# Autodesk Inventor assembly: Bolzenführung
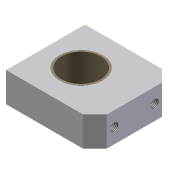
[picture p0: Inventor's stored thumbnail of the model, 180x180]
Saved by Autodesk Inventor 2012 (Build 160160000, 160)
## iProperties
Company: CAD-Verlag
Created: 2004-09
Part Number: Bolzenführung
Document SubType Name: Assembly
Designer: Greiling
Manufacturer: Standard
Standards Organization: Custom
Checked By: Jürgen Kronas
Stock Number: 10-10016
Author: Juergen Kronas
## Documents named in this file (3)
- C:\DemoDaten2012\CAD Daten\Daten Vault 2012 Inventor\Kapitel 4\Anschlag\Bolzenführung.iam
- C:\DemoDaten2012\CAD Daten\Daten Vault 2012 Inventor\Kapitel 4\Anschlag\Bolzenführung_einzel.ipt
- C:\DemoDaten2012\CAD Daten\Daten Vault 2012 Inventor\Kapitel 4\Anschlag\DU-Buchse.ipt
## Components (2 placed, 2 different names)
1. Bolzenführung_einzel:1 — Fluchtend:1
2. DU-Buchse:1 — Fluchtend:1
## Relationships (1: Flush 1)
- Fluchtend:1 [Flush]: Bolzenführung_einzel:1 ↔ DU-Buchse:1
